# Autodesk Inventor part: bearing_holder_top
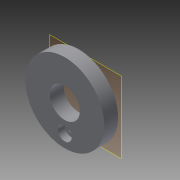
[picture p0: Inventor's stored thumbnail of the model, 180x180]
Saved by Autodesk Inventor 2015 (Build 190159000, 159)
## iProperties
Created: 2017-07
Part Number: bearing_holder_top
Material: Generic
Document SubType Name: Modeling
Designer: jonas
Density: 1 g/cm^3
Appearance: Default
Author: jonas
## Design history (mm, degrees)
workplane "Work Plane1"
sketch "Sketch1"
  geometry: C1 r 2.2 at (3.36, 10.128) reference; C2 r 2.2 at (9.66, -0.784) reference; C3 r 2.2 at (3.36, -11.696) reference; C4 r 2.2 at (-9.24, 10.128) reference; C5 r 2.2 at (-15.54, -0.784) reference; C6 r 2.2 at (-9.24, -11.696) reference; C7 r 16.1 at (-2.94, -0.784) reference; C8 r 6.5 at (-2.94, -0.784); C9 r 6.8 at (-2.94, -0.784) reference; 1 further point
  constraints: 1 centre point
extrude "Extrusion1" new body sketch "Sketch1" distance "d0" = 3; taper "d1" = 0 deg
sketch "Sketch2"
  geometry: C1 r 16.1 at (0, 0) reference; C2 r 6.8 at (0, 0) reference
extrude "Extrusion2" join sketch "Sketch2" distance "d2" = 3; taper "d3" = 0 deg
chamfer "Chamfer2" distance "d22" = 0.4; stored, may be unused: second distance "d23" = 2, angle "d24" = 45 deg
sketch "Sketch7"
  geometry: C1 r 1.5 at (0, -12) reference; 1 further point
hole "Hole4" sketch "Sketch7" at (0, -12) diameter "d32" = 3.5; stored, may be unused: countersink angle "d36" = 90 deg, drill point angle "d38" = 118 deg; dims "d33" = 6, "d34" = 6, "d35" = 3, "d37" = 8
workplane "Work Plane3"
body "Solid1"
node "Reference1"
node "Reference2"
node "Reference3"
node "Reference4"
node "Reference5"
node "Reference6"
node "Reference7"
node "Reference21"
node "Reference24"
node "Reference25"
node "Reference26"
